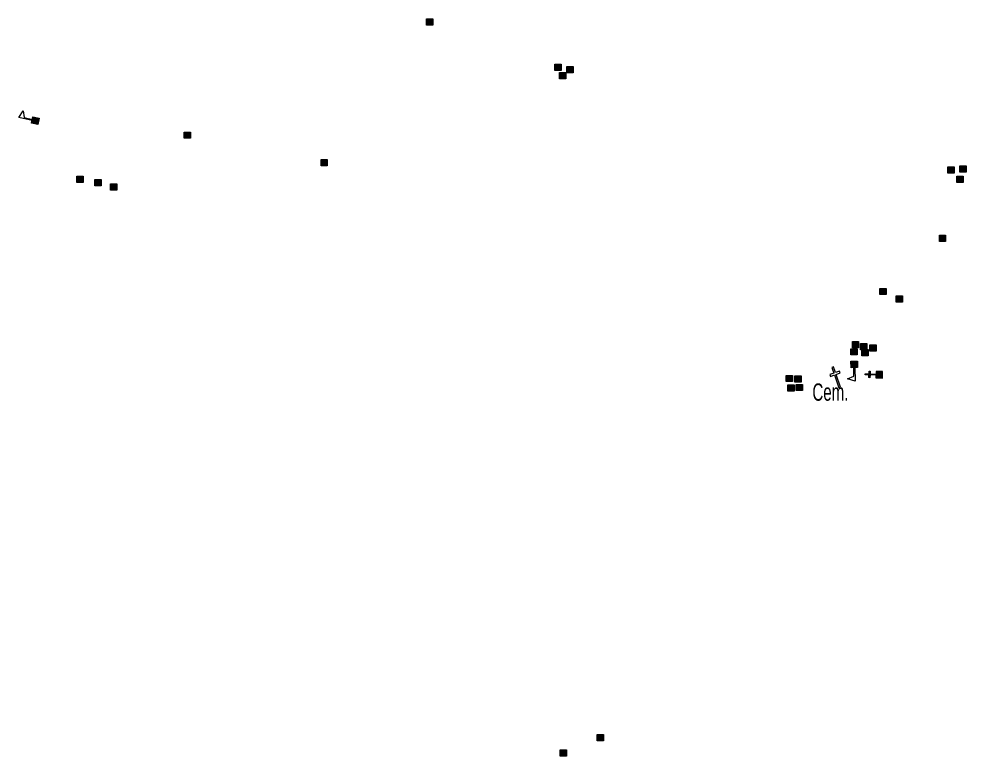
# Model space of a CAD drawing. Extents: x 647.8 to 672.9, y 6929.3 to 6957.3.
# Drawn here: x 649.788 to 654.16, y 6950.402 to 6953.806 of the extents above; entities that cross this region are included whole.
import ezdxf

# ---------------------------------------------------------------- set-up
doc = ezdxf.new("R2010")
doc.units = 0
doc.header["$LTSCALE"] = 0.032
for name, color, linetype, lineweight in [('2', 7, 'Continuous', 25), ('20', 7, 'Continuous', 25), ('4', 7, 'Continuous', 25), ('6', 7, 'Continuous', 25)]:
    doc.layers.add(name, color=color, linetype=linetype, lineweight=lineweight)
doc.layers.add('61', color=7, linetype='Continuous')

msp = doc.modelspace()

# ---------------------------------------------------------------- hatches: boundary and pattern name
at = {"layer": '2'}
for points in [[(651.6698, 6953.8055), (651.6988, 6953.8055), (651.6988, 6953.7765), (651.6698, 6953.7765)], [(652.2622, 6953.5971), (652.2912, 6953.5971), (652.2912, 6953.5681), (652.2622, 6953.5681)], [(652.2841, 6953.5576), (652.3131, 6953.5576), (652.3131, 6953.5286), (652.2841, 6953.5286)], [(652.317, 6953.5861), (652.346, 6953.5861), (652.346, 6953.5571), (652.317, 6953.5571)], [(650.551, 6953.2834), (650.58, 6953.2834), (650.58, 6953.2544), (650.551, 6953.2544)], [(651.1828, 6953.1561), (651.2118, 6953.1561), (651.2118, 6953.1271), (651.1828, 6953.1271)], [(654.0765, 6953.1232), (654.1055, 6953.1232), (654.1055, 6953.0942), (654.0765, 6953.0942)], [(654.1313, 6953.1276), (654.1603, 6953.1276), (654.1603, 6953.0986), (654.1313, 6953.0986)], [(650.0552, 6953.0794), (650.0842, 6953.0794), (650.0842, 6953.0504), (650.0552, 6953.0504)], [(654.1182, 6953.0794), (654.1472, 6953.0794), (654.1472, 6953.0504), (654.1182, 6953.0504)], [(650.1385, 6953.064), (650.1675, 6953.064), (650.1675, 6953.035), (650.1385, 6953.035)], [(650.2109, 6953.0443), (650.2399, 6953.0443), (650.2399, 6953.0153), (650.2109, 6953.0153)], [(654.037, 6952.8073), (654.066, 6952.8073), (654.066, 6952.7783), (654.037, 6952.7783)], [(653.7628, 6952.5616), (653.7918, 6952.5616), (653.7918, 6952.5326), (653.7628, 6952.5326)], [(653.8373, 6952.5265), (653.8663, 6952.5265), (653.8663, 6952.4975), (653.8373, 6952.4975)], [(653.6289, 6952.283), (653.6579, 6952.283), (653.6579, 6952.254), (653.6289, 6952.254)], [(653.6355, 6952.3159), (653.6645, 6952.3159), (653.6645, 6952.2869), (653.6355, 6952.2869)], [(653.6728, 6952.3071), (653.7018, 6952.3071), (653.7018, 6952.2781), (653.6728, 6952.2781)], [(653.7167, 6952.3005), (653.7457, 6952.3005), (653.7457, 6952.2715), (653.7167, 6952.2715)], [(653.6792, 6952.2788), (653.7082, 6952.2788), (653.7082, 6952.2498), (653.6792, 6952.2498)], [(653.3306, 6952.1601), (653.3596, 6952.1601), (653.3596, 6952.1311), (653.3306, 6952.1311)], [(653.3701, 6952.1579), (653.3991, 6952.1579), (653.3991, 6952.1289), (653.3701, 6952.1289)], [(653.3372, 6952.1163), (653.3662, 6952.1163), (653.3662, 6952.0873), (653.3372, 6952.0873)], [(653.3766, 6952.1185), (653.4056, 6952.1185), (653.4056, 6952.0895), (653.3766, 6952.0895)], [(652.4574, 6950.5016), (652.4864, 6950.5016), (652.4864, 6950.4726), (652.4574, 6950.4726)], [(652.2863, 6950.4314), (652.3153, 6950.4314), (652.3153, 6950.4024), (652.2863, 6950.4024)]]:
    msp.add_hatch(color=256, dxfattribs=at).paths.add_polyline_path(points)
at = {"layer": '4'}
for points in [[(649.8761, 6953.3184), (649.8468, 6953.3249), (649.8532, 6953.3542), (649.8825, 6953.3477)], [(653.6585, 6952.2259), (653.6593, 6952.1959), (653.6293, 6952.1951), (653.6285, 6952.2251)]]:
    msp.add_hatch(color=256, dxfattribs=at).paths.add_polyline_path(points)
at = {"layer": '6'}
for points in [[(653.7449, 6952.1658), (653.7447, 6952.1608), (653.7172, 6952.1618), (653.7167, 6952.1493), (653.7117, 6952.1495), (653.7122, 6952.162), (653.6947, 6952.1626), (653.6949, 6952.1676), (653.7124, 6952.167), (653.7128, 6952.1794), (653.7178, 6952.1793), (653.7174, 6952.1668)], [(653.7442, 6952.1483), (653.7742, 6952.1473), (653.7753, 6952.1772), (653.7453, 6952.1783)]]:
    msp.add_hatch(color=256, dxfattribs=at).paths.add_polyline_path(points)

# ---------------------------------------------------------------- linework, layer by layer
at = {"layer": '2'}
for points in [[(651.6698, 6953.8055), (651.6988, 6953.8055), (651.6988, 6953.7765), (651.6698, 6953.7765)], [(652.2622, 6953.5971), (652.2912, 6953.5971), (652.2912, 6953.5681), (652.2622, 6953.5681)], [(652.2841, 6953.5576), (652.3131, 6953.5576), (652.3131, 6953.5286), (652.2841, 6953.5286)], [(652.317, 6953.5861), (652.346, 6953.5861), (652.346, 6953.5571), (652.317, 6953.5571)], [(650.551, 6953.2834), (650.58, 6953.2834), (650.58, 6953.2544), (650.551, 6953.2544)], [(651.1828, 6953.1561), (651.2118, 6953.1561), (651.2118, 6953.1271), (651.1828, 6953.1271)], [(654.0765, 6953.1232), (654.1055, 6953.1232), (654.1055, 6953.0942), (654.0765, 6953.0942)], [(654.1313, 6953.1276), (654.1603, 6953.1276), (654.1603, 6953.0986), (654.1313, 6953.0986)], [(650.0552, 6953.0794), (650.0842, 6953.0794), (650.0842, 6953.0504), (650.0552, 6953.0504)], [(654.1182, 6953.0794), (654.1472, 6953.0794), (654.1472, 6953.0504), (654.1182, 6953.0504)], [(650.1385, 6953.064), (650.1675, 6953.064), (650.1675, 6953.035), (650.1385, 6953.035)], [(650.2109, 6953.0443), (650.2399, 6953.0443), (650.2399, 6953.0153), (650.2109, 6953.0153)], [(654.037, 6952.8073), (654.066, 6952.8073), (654.066, 6952.7783), (654.037, 6952.7783)], [(653.7628, 6952.5616), (653.7918, 6952.5616), (653.7918, 6952.5326), (653.7628, 6952.5326)], [(653.8373, 6952.5265), (653.8663, 6952.5265), (653.8663, 6952.4975), (653.8373, 6952.4975)], [(653.6289, 6952.283), (653.6579, 6952.283), (653.6579, 6952.254), (653.6289, 6952.254)], [(653.6355, 6952.3159), (653.6645, 6952.3159), (653.6645, 6952.2869), (653.6355, 6952.2869)], [(653.6728, 6952.3071), (653.7018, 6952.3071), (653.7018, 6952.2781), (653.6728, 6952.2781)], [(653.7167, 6952.3005), (653.7457, 6952.3005), (653.7457, 6952.2715), (653.7167, 6952.2715)], [(653.6792, 6952.2788), (653.7082, 6952.2788), (653.7082, 6952.2498), (653.6792, 6952.2498)], [(653.3306, 6952.1601), (653.3596, 6952.1601), (653.3596, 6952.1311), (653.3306, 6952.1311)], [(653.3701, 6952.1579), (653.3991, 6952.1579), (653.3991, 6952.1289), (653.3701, 6952.1289)], [(653.3372, 6952.1163), (653.3662, 6952.1163), (653.3662, 6952.0873), (653.3372, 6952.0873)], [(653.3766, 6952.1185), (653.4056, 6952.1185), (653.4056, 6952.0895), (653.3766, 6952.0895)], [(652.4574, 6950.5016), (652.4864, 6950.5016), (652.4864, 6950.4726), (652.4574, 6950.4726)], [(652.2863, 6950.4314), (652.3153, 6950.4314), (652.3153, 6950.4024), (652.2863, 6950.4024)]]:
    msp.add_lwpolyline(points, close=True, dxfattribs=at)
at = {"layer": '20'}
for points in [[(653.5574, 6952.1727), (653.5482, 6952.1991), (653.5407, 6952.1965), (653.5499, 6952.17)], [(653.5499, 6952.17), (653.531, 6952.1634), (653.5338, 6952.1555), (653.5527, 6952.162), (653.5736, 6952.1021)], [(653.5602, 6952.1647), (653.5791, 6952.1713), (653.5763, 6952.1793), (653.5574, 6952.1727)], [(653.5736, 6952.1021), (653.5811, 6952.1048), (653.5602, 6952.1647)]]:
    msp.add_lwpolyline(points, dxfattribs=at)
at = {"layer": '4'}
for p, q in [((649.8495, 6953.3371), (649.8505, 6953.342)), ((653.6468, 6952.1956), (653.6418, 6952.1954))]:
    msp.add_line(p, q, dxfattribs=at)
for points in [[(649.8495, 6953.3371), (649.7884, 6953.3505), (649.8081, 6953.382), (649.812, 6953.3504), (649.8505, 6953.342)], [(649.8761, 6953.3184), (649.8468, 6953.3249), (649.8532, 6953.3542), (649.8825, 6953.3477)], [(653.6468, 6952.1956), (653.6484, 6952.1331), (653.6131, 6952.1447), (653.6428, 6952.1559), (653.6418, 6952.1954)], [(653.6585, 6952.2259), (653.6593, 6952.1959), (653.6293, 6952.1951), (653.6285, 6952.2251)]]:
    msp.add_lwpolyline(points, close=True, dxfattribs=at)
at = {"layer": '6'}
for points in [[(653.7449, 6952.1658), (653.7447, 6952.1608), (653.7172, 6952.1618), (653.7167, 6952.1493), (653.7117, 6952.1495), (653.7122, 6952.162), (653.6947, 6952.1626), (653.6949, 6952.1676), (653.7124, 6952.167), (653.7128, 6952.1794), (653.7178, 6952.1793), (653.7174, 6952.1668)], [(653.7442, 6952.1483), (653.7742, 6952.1473), (653.7753, 6952.1772), (653.7453, 6952.1783)]]:
    msp.add_lwpolyline(points, close=True, dxfattribs=at)

# ---------------------------------------------------------------- texts
at = {"layer": '61', "width": 0.65}
msp.add_text('Cem.', height=0.08, dxfattribs=at).set_placement((653.4511, 6952.0428))

doc.saveas('drawing.dxf')
